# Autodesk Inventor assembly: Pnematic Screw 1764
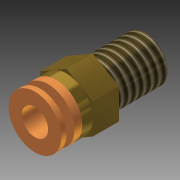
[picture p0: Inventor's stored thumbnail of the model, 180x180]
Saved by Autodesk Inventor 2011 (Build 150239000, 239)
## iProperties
Created: 2010-02
Part Number: Pnematic Screw 1764
Document SubType Name: Assembly
Designer: clee1
Author: clee1
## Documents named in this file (3)
- R:\CAD Archives\Pnewmatics\pnewmatic screw\Pnematic Screw 1764.iam
- R:\CAD Archives\Pnewmatics\pnewmatic screw\Pnewmatic Screw Part 1 1764.ipt
- R:\CAD Archives\Pnewmatics\pnewmatic screw\Pnewmatic Screw Part 2 1764.ipt
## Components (2 placed, 2 different names)
1. Pnewmatic Screw Part 1 1764:1 — Insert:1
2. Pnewmatic Screw Part 2 1764:1 — Insert:1
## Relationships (1: Insert 1)
- Insert:1: Pnewmatic Screw Part 1 1764:1 ↔ Pnewmatic Screw Part 2 1764:1
